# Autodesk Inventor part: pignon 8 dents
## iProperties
Shininess: 64.0
Length Units: 11269
Angle Units: 11279
Time Units: 11290
Mass Units: 11283
Length Display Precision: 3
Angle Display Precision: 2
Compacted: True
Part Number: pignon 8 dents
Document SubType Name: Modeling
Created: 2004-09
Material: Par défaut
Designer: Laurent
Density: 1 g/cm^3
Density: 0.0
Volumn: 0.0
Area: 0.0
PropertySet Name: Model Information
Control State: 0
Master: False
Checked Out: False
Author: Laurent
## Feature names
1. Extrusion1
